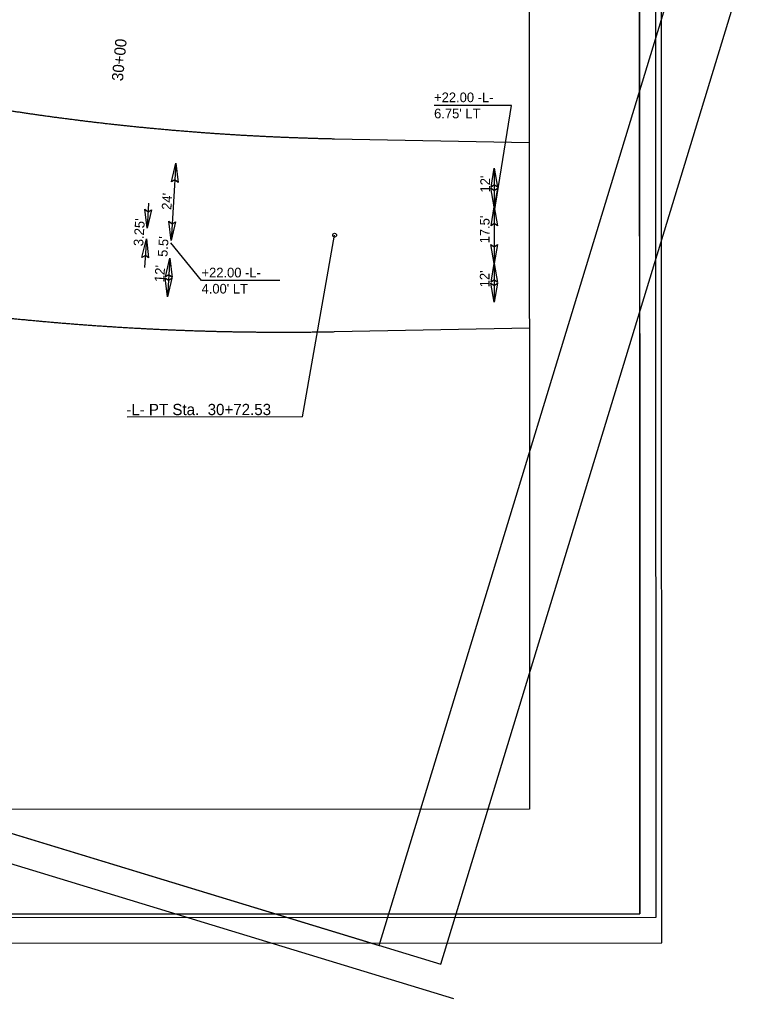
# Model space of a CAD drawing. Extents: x 1443477 to 1619989, y 756574 to 899826.
# Drawn here: x 1619701.9 to 1619930.2, y 897804.7 to 898108 of the extents above; entities that cross this region are included whole.
import ezdxf

# ---------------------------------------------------------------- set-up
doc = ezdxf.new("R2010")
doc.units = 0
for name, color, linetype in [('Default', 7, 'Continuous'), ('Prop Conc 2ft 6in Curb and Gutter', 7, 'Continuous'), ('Prop Dimension', 7, 'Continuous'), ('Prop Guardrail', 7, 'Continuous'), ('Prop Horizontal Alignment Station Label', 7, 'Continuous'), ('Prop Horizontal Alignment Tick Label', 7, 'Continuous'), ('Prop Terminator CELL', 7, 'Continuous'), ('Sheet Clip Boundary CELL', 7, 'Continuous'), ('Sheet Cutting Line CELL', 7, 'Continuous'), ('Sheet Layout Plan Border', 7, 'Continuous'), ('Sheet Plan CELL', 7, 'Continuous'), ('Sheet Plan Layout CELL', 7, 'Continuous'), ('Sheet Plot Border Inside CELL', 7, 'Continuous'), ('Sheet Plot Border Outside CELL', 7, 'Continuous')]:
    doc.layers.add(name, color=color, linetype=linetype)

msp = doc.modelspace()

# ---------------------------------------------------------------- linework, layer by layer
at = {"layer": 'Default'}
msp.add_lwpolyline([(1619324.8, 898243.59), (1619813.94, 898243.79), (1619813.98, 898167.39), (1619859.81, 898167.41), (1619859.94, 897863.4), (1619324.96, 897863.18)], close=True, dxfattribs=at)
at = {"layer": 'Prop Conc 2ft 6in Curb and Gutter'}
for p, q in [((1619854.28, 898081.45), (1619830.34, 898081.44)), ((1619848.99, 898047.99), (1619854.28, 898081.45)), ((1619758.26, 898027.15), (1619748.77, 898038.84)), ((1619782.54, 898027.16), (1619758.26, 898027.15))]:
    msp.add_line(p, q, dxfattribs=at)
at = {"layer": 'Prop Dimension'}
for p, q in [((1619750.33, 898063.54), (1619748.81, 898039.59)), ((1619848.99, 898061.99), (1619848.99, 898049.99)), ((1619741.87, 898051.12), (1619741.38, 898043.36)), ((1619848.99, 898049.99), (1619848.99, 898032.49)), ((1619741.17, 898040.11), (1619740.61, 898031.23)), ((1619748.47, 898034.1), (1619747.71, 898022.13)), ((1619848.99, 898032.49), (1619848.99, 898020.49))]:
    msp.add_line(p, q, dxfattribs=at)
at = {"layer": 'Prop Guardrail'}
for p, q in [((1619859.85, 898069.83), (1619799.51, 898071.03)), ((1619799.51, 898011.35), (1619859.87, 898012.55))]:
    msp.add_line(p, q, dxfattribs=at)
for points in [[(1619703.74, 898079.02), (1619702.45, 898079.21), (1619701.81, 898079.31), (1619701.17, 898079.4), (1619700.53, 898079.5), (1619699.89, 898079.6), (1619699.25, 898079.69), (1619698.6, 898079.79), (1619697.96, 898079.89), (1619697.32, 898079.99), (1619696.68, 898080.09), (1619696.04, 898080.19), (1619695.4, 898080.29), (1619694.76, 898080.39), (1619694.12, 898080.5), (1619693.48, 898080.6), (1619692.84, 898080.7), (1619692.2, 898080.81), (1619691.56, 898080.91), (1619690.92, 898081.01), (1619690.28, 898081.12), (1619689.64, 898081.23), (1619689, 898081.33), (1619688.36, 898081.44), (1619687.72, 898081.55), (1619687.08, 898081.65), (1619686.44, 898081.76), (1619685.8, 898081.87), (1619685.16, 898081.98), (1619684.52, 898082.09), (1619683.88, 898082.2), (1619683.24, 898082.31), (1619682.6, 898082.43), (1619681.96, 898082.54), (1619681.32, 898082.65), (1619680.69, 898082.76), (1619680.05, 898082.88), (1619679.41, 898082.99), (1619678.77, 898083.11), (1619678.13, 898083.22), (1619677.49, 898083.34), (1619676.86, 898083.46), (1619676.22, 898083.57), (1619675.58, 898083.69), (1619674.94, 898083.81), (1619674.31, 898083.93), (1619673.67, 898084.05), (1619673.03, 898084.17), (1619672.39, 898084.29), (1619671.76, 898084.41), (1619671.12, 898084.53), (1619670.48, 898084.65), (1619669.85, 898084.78), (1619669.21, 898084.9), (1619668.57, 898085.02), (1619667.94, 898085.15), (1619667.3, 898085.27), (1619666.67, 898085.4), (1619666.03, 898085.52), (1619665.39, 898085.65), (1619664.76, 898085.78), (1619664.12, 898085.9), (1619663.49, 898086.03), (1619662.85, 898086.16), (1619662.22, 898086.29), (1619661.58, 898086.42), (1619660.95, 898086.55), (1619660.31, 898086.68), (1619659.68, 898086.81), (1619659.04, 898086.94), (1619658.41, 898087.07), (1619657.77, 898087.21), (1619657.14, 898087.34), (1619656.5, 898087.47)], [(1619751.47, 898073.53), (1619750.18, 898073.64), (1619749.53, 898073.69), (1619748.88, 898073.75), (1619748.23, 898073.81), (1619747.59, 898073.86), (1619746.94, 898073.92), (1619746.29, 898073.98), (1619745.65, 898074.04), (1619745, 898074.1), (1619744.35, 898074.16), (1619743.7, 898074.22), (1619743.06, 898074.28), (1619742.41, 898074.34), (1619741.76, 898074.4), (1619741.12, 898074.46), (1619740.47, 898074.53), (1619739.82, 898074.59), (1619739.18, 898074.65), (1619738.53, 898074.72), (1619737.89, 898074.78), (1619737.24, 898074.85), (1619736.59, 898074.92), (1619735.95, 898074.98), (1619735.3, 898075.05), (1619734.65, 898075.12), (1619734.01, 898075.19), (1619733.36, 898075.26), (1619732.72, 898075.33), (1619732.07, 898075.4), (1619731.43, 898075.47), (1619730.78, 898075.54), (1619730.13, 898075.61), (1619729.49, 898075.68), (1619728.84, 898075.75), (1619728.2, 898075.83), (1619727.55, 898075.9), (1619726.91, 898075.98), (1619726.26, 898076.05), (1619725.62, 898076.13), (1619724.97, 898076.2), (1619724.33, 898076.28), (1619723.68, 898076.36), (1619723.04, 898076.44), (1619722.4, 898076.51), (1619721.75, 898076.59), (1619721.11, 898076.67), (1619720.46, 898076.75), (1619719.82, 898076.83), (1619719.17, 898076.91), (1619718.53, 898076.99), (1619717.89, 898077.08), (1619717.24, 898077.16), (1619716.6, 898077.24), (1619715.95, 898077.33), (1619715.31, 898077.41), (1619714.67, 898077.5), (1619714.02, 898077.58), (1619713.38, 898077.67), (1619712.74, 898077.75), (1619712.09, 898077.84), (1619711.45, 898077.93), (1619710.81, 898078.02), (1619710.16, 898078.1), (1619709.52, 898078.19), (1619708.88, 898078.28), (1619708.24, 898078.37), (1619707.59, 898078.46), (1619706.95, 898078.56), (1619706.31, 898078.65), (1619705.67, 898078.74), (1619705.02, 898078.83), (1619704.38, 898078.93), (1619703.74, 898079.02)], [(1619799.51, 898071.03), (1619798.21, 898071.05), (1619797.56, 898071.07), (1619796.91, 898071.09), (1619796.26, 898071.1), (1619795.61, 898071.12), (1619794.96, 898071.13), (1619794.31, 898071.15), (1619793.66, 898071.17), (1619793.01, 898071.19), (1619792.36, 898071.21), (1619791.71, 898071.23), (1619791.06, 898071.25), (1619790.41, 898071.27), (1619789.76, 898071.29), (1619789.11, 898071.31), (1619788.46, 898071.34), (1619787.81, 898071.36), (1619787.16, 898071.38), (1619786.51, 898071.41), (1619785.86, 898071.43), (1619785.21, 898071.46), (1619784.56, 898071.48), (1619783.91, 898071.51), (1619783.26, 898071.54), (1619782.61, 898071.56), (1619781.96, 898071.59), (1619781.31, 898071.62), (1619780.66, 898071.65), (1619780.01, 898071.68), (1619779.36, 898071.71), (1619778.71, 898071.74), (1619778.06, 898071.77), (1619777.41, 898071.8), (1619776.76, 898071.84), (1619776.11, 898071.87), (1619775.46, 898071.9), (1619774.82, 898071.94), (1619774.17, 898071.97), (1619773.52, 898072.01), (1619772.87, 898072.04), (1619772.22, 898072.08), (1619771.57, 898072.12), (1619770.92, 898072.15), (1619770.27, 898072.19), (1619769.62, 898072.23), (1619768.97, 898072.27), (1619768.32, 898072.31), (1619767.68, 898072.35), (1619767.03, 898072.39), (1619766.38, 898072.43), (1619765.73, 898072.47), (1619765.08, 898072.51), (1619764.43, 898072.56), (1619763.78, 898072.6), (1619763.14, 898072.64), (1619762.49, 898072.69), (1619761.84, 898072.73), (1619761.19, 898072.78), (1619760.54, 898072.83), (1619759.89, 898072.87), (1619759.25, 898072.92), (1619758.6, 898072.97), (1619757.95, 898073.02), (1619757.3, 898073.06), (1619756.65, 898073.11), (1619756, 898073.16), (1619755.36, 898073.21), (1619754.71, 898073.26), (1619754.06, 898073.32), (1619753.41, 898073.37), (1619752.77, 898073.42), (1619752.12, 898073.47), (1619751.47, 898073.53)], [(1619695.8, 898015.84), (1619697.2, 898015.69), (1619697.9, 898015.62), (1619698.59, 898015.55), (1619699.29, 898015.47), (1619699.99, 898015.4), (1619700.69, 898015.33), (1619701.39, 898015.26), (1619702.09, 898015.19), (1619702.79, 898015.12), (1619703.49, 898015.06), (1619704.19, 898014.99), (1619704.89, 898014.92), (1619705.59, 898014.86), (1619706.29, 898014.79), (1619706.99, 898014.73), (1619707.69, 898014.66), (1619708.39, 898014.6), (1619709.09, 898014.53), (1619709.79, 898014.47), (1619710.48, 898014.41), (1619711.18, 898014.35), (1619711.88, 898014.29), (1619712.58, 898014.23), (1619713.28, 898014.17), (1619713.98, 898014.11), (1619714.68, 898014.05), (1619715.38, 898013.99), (1619716.08, 898013.93), (1619716.78, 898013.88), (1619717.48, 898013.82), (1619718.18, 898013.77), (1619718.89, 898013.71), (1619719.59, 898013.66), (1619720.29, 898013.6), (1619720.99, 898013.55), (1619721.69, 898013.5), (1619722.39, 898013.45), (1619723.09, 898013.39), (1619723.79, 898013.34), (1619724.49, 898013.29), (1619725.19, 898013.24), (1619725.89, 898013.19), (1619726.59, 898013.15), (1619727.29, 898013.1), (1619727.99, 898013.05), (1619728.69, 898013), (1619729.39, 898012.96), (1619730.09, 898012.91), (1619730.79, 898012.87), (1619731.49, 898012.82), (1619732.2, 898012.78), (1619732.9, 898012.74), (1619733.6, 898012.69), (1619734.3, 898012.65), (1619735, 898012.61), (1619735.7, 898012.57), (1619736.4, 898012.53), (1619737.1, 898012.49), (1619737.8, 898012.45), (1619738.5, 898012.41), (1619739.2, 898012.38), (1619739.91, 898012.34), (1619740.61, 898012.3), (1619741.31, 898012.27), (1619742.01, 898012.23), (1619742.71, 898012.2), (1619743.41, 898012.16), (1619744.11, 898012.13), (1619744.81, 898012.1), (1619745.51, 898012.06), (1619746.22, 898012.03), (1619746.92, 898012), (1619747.62, 898011.97)], [(1619747.62, 898011.97), (1619749.02, 898011.91), (1619749.72, 898011.88), (1619750.42, 898011.85), (1619751.12, 898011.82), (1619751.83, 898011.8), (1619752.53, 898011.77), (1619753.23, 898011.75), (1619753.93, 898011.72), (1619754.63, 898011.7), (1619755.33, 898011.67), (1619756.03, 898011.65), (1619756.74, 898011.62), (1619757.44, 898011.6), (1619758.14, 898011.58), (1619758.84, 898011.56), (1619759.54, 898011.54), (1619760.24, 898011.52), (1619760.94, 898011.5), (1619761.64, 898011.48), (1619762.35, 898011.46), (1619763.05, 898011.44), (1619763.75, 898011.43), (1619764.45, 898011.41), (1619765.15, 898011.4), (1619765.85, 898011.38), (1619766.55, 898011.37), (1619767.26, 898011.35), (1619767.96, 898011.34), (1619768.66, 898011.33), (1619769.36, 898011.31), (1619770.06, 898011.3), (1619770.76, 898011.29), (1619771.46, 898011.28), (1619772.17, 898011.27), (1619772.87, 898011.26), (1619773.57, 898011.25), (1619774.27, 898011.24), (1619774.97, 898011.24), (1619775.67, 898011.23), (1619776.37, 898011.22), (1619777.08, 898011.22), (1619777.78, 898011.21), (1619778.48, 898011.21), (1619779.18, 898011.2), (1619779.88, 898011.2), (1619780.58, 898011.2), (1619781.28, 898011.2), (1619781.99, 898011.19), (1619782.69, 898011.19), (1619783.39, 898011.19), (1619784.09, 898011.19), (1619784.79, 898011.19), (1619785.49, 898011.19), (1619786.19, 898011.2), (1619786.89, 898011.2), (1619787.6, 898011.2), (1619788.3, 898011.21), (1619789, 898011.21), (1619789.7, 898011.22), (1619790.4, 898011.22), (1619791.1, 898011.23), (1619791.8, 898011.23), (1619792.5, 898011.24), (1619793.2, 898011.25), (1619793.91, 898011.26), (1619794.61, 898011.27), (1619795.31, 898011.28), (1619796.01, 898011.29), (1619796.71, 898011.3), (1619797.41, 898011.31), (1619798.11, 898011.32), (1619798.81, 898011.33), (1619799.51, 898011.35)]]:
    msp.add_spline(points, degree=3, dxfattribs=at)
at = {"layer": 'Prop Horizontal Alignment Station Label'}
for q in [(1619799.51, 898041.24), (1619735.26, 897984.89)]:
    msp.add_line((1619789.56, 897984.92), q, dxfattribs=at)
msp.add_circle((1619799.51, 898041.24), 0.6, dxfattribs=at)
at = {"layer": 'Prop Terminator CELL'}
for points in [[(1619748.95, 898057.77), (1619750.33, 898063.54), (1619751, 898057.61), (1619750, 898058.42)], [(1619847.98, 898056.14), (1619848.99, 898061.99), (1619850.03, 898056.11), (1619848.99, 898056.86)], [(1619849.99, 898055.84), (1619848.99, 898049.99), (1619847.95, 898055.87), (1619848.99, 898055.13)], [(1619742.75, 898049.13), (1619741.38, 898043.36), (1619740.71, 898049.29), (1619741.7, 898048.48)], [(1619847.98, 898044.14), (1619848.99, 898049.99), (1619850.03, 898044.11), (1619848.99, 898044.86)], [(1619750.19, 898045.37), (1619748.81, 898039.59), (1619748.15, 898045.53), (1619749.14, 898044.72)], [(1619739.8, 898034.34), (1619741.17, 898040.11), (1619741.84, 898034.18), (1619740.85, 898034.99)], [(1619849.99, 898038.34), (1619848.99, 898032.49), (1619847.95, 898038.37), (1619848.99, 898037.63)], [(1619747.09, 898028.33), (1619748.47, 898034.1), (1619749.13, 898028.17), (1619748.14, 898028.98)], [(1619847.98, 898026.64), (1619848.99, 898032.49), (1619850.03, 898026.61), (1619848.99, 898027.36)], [(1619749.08, 898027.9), (1619747.71, 898022.13), (1619747.04, 898028.06), (1619748.03, 898027.25)], [(1619849.99, 898026.34), (1619848.99, 898020.49), (1619847.95, 898026.37), (1619848.99, 898025.63)]]:
    msp.add_lwpolyline(points, close=True, dxfattribs=at)
at = {"layer": 'Sheet Clip Boundary CELL'}
msp.add_lwpolyline([(1619277.64, 897984.43), (1619813.32, 897821.17), (1619911.11, 898142), (1619838.69, 898164.07), (1619863.35, 898244.99), (1619400.09, 898386.19)], close=True, dxfattribs=at)
at = {"layer": 'Sheet Cutting Line CELL'}
msp.add_line((1619192.19, 898001.07), (1619836.33, 897804.74), dxfattribs=at)
at = {"layer": 'Sheet Layout Plan Border'}
msp.add_lwpolyline([(1619277.64, 897984.43), (1619813.32, 897821.17), (1619911.11, 898142), (1619838.69, 898164.07), (1619863.35, 898244.99), (1619400.09, 898386.19)], close=True, dxfattribs=at)
at = {"layer": 'Sheet Plan CELL'}
for points in [[(1619294.13, 897830.71), (1619293.94, 898250.7), (1619813.94, 898250.93), (1619813.97, 898190.91), (1619893.98, 898190.94), (1619894.13, 897830.96)], [(1619893.97, 898250.96), (1619293.95, 898250.71), (1619294.13, 897830.71), (1619894.13, 897830.96)]]:
    msp.add_lwpolyline(points, close=True, dxfattribs=at)
at = {"layer": 'Sheet Plan Layout CELL'}
msp.add_lwpolyline([(1619380.95, 898392.01), (1619258.51, 897990.27), (1619832.45, 897815.34), (1619930.23, 898136.17), (1619838.69, 898164.07), (1619863.35, 898244.99)], close=True, dxfattribs=at)
at = {"layer": 'Sheet Plot Border Inside CELL'}
msp.add_lwpolyline([(1619232.74, 897829.68), (1619899.13, 897829.97), (1619898.96, 898251.96), (1619232.56, 898251.68)], close=True, dxfattribs=at)
at = {"layer": 'Sheet Plot Border Outside CELL'}
msp.add_lwpolyline([(1619227.54, 897821.68), (1619900.94, 897821.96), (1619900.76, 898259.96), (1619227.36, 898259.68)], close=True, dxfattribs=at)

# ---------------------------------------------------------------- texts
at = {"layer": 'Prop Conc 2ft 6in Curb and Gutter'}
for s, p in [('+22.00 -L-', (1619830.34, 898082.44)), ("6.75' LT", (1619830.34, 898077.44)), ('+22.00 -L-', (1619758.26, 898028.15)), ("4.00' LT", (1619758.27, 898023.15))]:
    msp.add_text(s, height=3, rotation=0.0239, dxfattribs=at).set_placement(p)
at = {"layer": 'Prop Dimension'}
for s, rotation, p in [("12'", 90, (1619847.65, 898054.47)), ("24'", 86.3812, (1619748.89, 898048.99)), ("3.25'", 86.3812, (1619740.17, 898037.76)), ("17.5'", 90, (1619847.52, 898038.71)), ("5.5'", 86.3812, (1619747.68, 898034.44)), ("12'", 86.3812, (1619746.66, 898026.61)), ("12'", 90, (1619847.52, 898025.09))]:
    msp.add_text(s, height=3, rotation=rotation, dxfattribs=at).set_placement(p)
at = {"layer": 'Prop Horizontal Alignment Station Label'}
msp.add_text('-L- PT Sta.  30+72.53', height=3.5, rotation=0.0239, dxfattribs=at).set_placement((1619734.93, 897985.46))
at = {"layer": 'Prop Horizontal Alignment Tick Label'}
msp.add_text('30+00', height=3.5, rotation=84.8056, dxfattribs=at).set_placement((1619733.89, 898088.85))

doc.saveas('drawing.dxf')
